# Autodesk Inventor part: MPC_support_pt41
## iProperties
Shininess: 64.0
Length Units: 11272
Angle Units: 11279
Time Units: 11290
Mass Units: 11286
Length Display Precision: 3
Angle Display Precision: 2
Compacted: True
Part Number: MPC_support_pt41
Document SubType Name: Modeling
Created: 2004-08
Designer: John Blackburn
Material: Stainless Steel, Austenitic
Manufacturer: Standard
Standards Organization: Custom
Density: 0.0
Volumn: 0.0
Area: 0.0
PropertySet Name: Model Information
Control State: 0
Master: False
Checked Out: False
Author: John Blackburn
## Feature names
1. Base1
